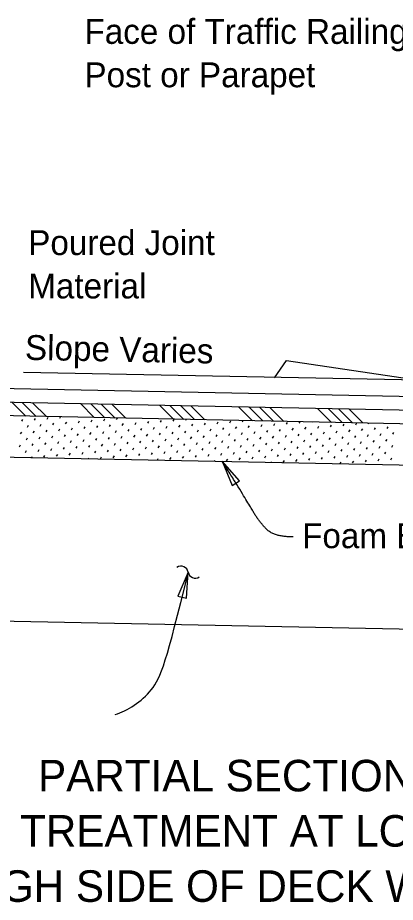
# Model space of a CAD drawing. Extents: x -7.9 to 27, y -3.1 to 14.6.
# Drawn here: x 11.534 to 12.683, y 7.031 to 9.722 of the extents above; entities that cross this region are included whole.
import ezdxf

# ---------------------------------------------------------------- set-up
doc = ezdxf.new("R2010")
doc.units = 0
for name, color, linetype in [('Border', 7, 'Continuous'), ('Patterning', 7, 'Continuous'), ('PlotBorder_dp', 7, 'Continuous'), ('TextMisc', 7, 'Continuous')]:
    doc.layers.add(name, color=color, linetype=linetype)

msp = doc.modelspace()

# ---------------------------------------------------------------- linework, layer by layer
at = {"layer": 'Patterning'}
for p, q in [((11.429, 8.5953), (13.3109, 8.5576)), ((14.5636, 7.8243), (11.2433, 7.8907))]:
    msp.add_line(p, q, dxfattribs=at)
at = {"layer": 'PlotBorder_dp'}
msp.add_lwpolyline([(12.3148, 8.6261), (12.3513, 8.6785), (12.7548, 8.6186), (11.5512, 8.6426)], dxfattribs=at)
for points in [[(12.1563, 8.3723), (12.1863, 8.299), (12.2088, 8.313)], [(12.0528, 8.0347), (12.0215, 7.9619), (12.0472, 7.9557)]]:
    msp.add_lwpolyline(points, close=True, dxfattribs=at)
for centre, start, end in [((12.0306, 8.0307), 10.958, 122.6852), ((12.0744, 8.0392), 190.958, 302.6852)]:
    msp.add_arc(centre, 0.0224, start, end, dxfattribs=at)
for points, degree in [([(12.3717, 8.142), (12.3138, 8.142), (12.2671, 8.1901), (12.2339, 8.2479), (12.1563, 8.3723)], 2), ([(11.8306, 7.6017), (11.8678, 7.6136), (11.9536, 7.6667), (11.9866, 7.7626), (12.0527, 8.0347)], 3)]:
    msp.add_open_spline(points, degree=degree, dxfattribs=at)
at = {"layer": 'TextMisc'}
for p, q in [((11.2433, 8.5573), (13.3732, 8.5146)), ((11.5157, 8.5518), (11.5583, 8.5093)), ((11.5475, 8.5512), (11.5901, 8.5086)), ((11.5794, 8.5505), (11.6219, 8.508)), ((11.7245, 8.5476), (11.767, 8.5051)), ((11.7563, 8.547), (11.7989, 8.5044)), ((11.7881, 8.5464), (11.8307, 8.5038)), ((11.82, 8.5457), (11.8625, 8.5032)), ((11.9651, 8.5428), (12.0076, 8.5003)), ((11.9969, 8.5422), (12.0394, 8.4996)), ((12.0287, 8.5416), (12.0713, 8.499)), ((12.0606, 8.5409), (12.1031, 8.4984)), ((12.2056, 8.538), (12.2482, 8.4954)), ((12.2375, 8.5374), (12.28, 8.4948)), ((12.2693, 8.5367), (12.3119, 8.4942)), ((12.3012, 8.5361), (12.3437, 8.4935)), ((12.4462, 8.5332), (12.4888, 8.4906)), ((12.4781, 8.5326), (12.5206, 8.49)), ((12.5099, 8.5319), (12.5525, 8.4894)), ((12.5417, 8.5313), (12.5843, 8.4887)), ((13.3724, 8.4729), (11.2433, 8.5156)), ((11.6233, 8.5004), (11.6266, 8.506)), ((11.662, 8.5037), (11.664, 8.5071)), ((11.8344, 8.4989), (11.8371, 8.5037)), ((11.546, 8.4939), (11.5492, 8.4995)), ((11.5637, 8.4762), (11.5669, 8.4818)), ((11.5846, 8.4972), (11.5879, 8.5028)), ((11.6024, 8.4795), (11.6056, 8.4851)), ((11.641, 8.4827), (11.6443, 8.4883)), ((11.6797, 8.4859), (11.6829, 8.4915)), ((11.7184, 8.4892), (11.7216, 8.4948)), ((11.7361, 8.4715), (11.7393, 8.4771)), ((11.757, 8.4924), (11.7603, 8.498)), ((11.7747, 8.4747), (11.778, 8.4803)), ((11.7957, 8.4957), (11.7989, 8.5013)), ((11.8134, 8.4779), (11.8167, 8.4835)), ((11.8521, 8.4812), (11.8553, 8.4868)), ((11.873, 8.5021), (11.8735, 8.5029)), ((11.8908, 8.4844), (11.894, 8.49)), ((11.9294, 8.4877), (11.9327, 8.4933)), ((11.9681, 8.4909), (11.9713, 8.4965)), ((11.9858, 8.4732), (11.9891, 8.4788)), ((12.0068, 8.4942), (12.01, 8.4998)), ((12.0245, 8.4764), (12.0277, 8.482)), ((12.0454, 8.4974), (12.0466, 8.4995)), ((12.0632, 8.4797), (12.0664, 8.4853)), ((12.1018, 8.4829), (12.1051, 8.4885)), ((12.1405, 8.4862), (12.1437, 8.4918)), ((12.1792, 8.4894), (12.1824, 8.495)), ((12.1969, 8.4717), (12.2001, 8.4773)), ((12.2178, 8.4926), (12.2198, 8.496)), ((12.2355, 8.4749), (12.2388, 8.4805)), ((12.2742, 8.4782), (12.2775, 8.4838)), ((12.3129, 8.4814), (12.3161, 8.487)), ((12.3516, 8.4847), (12.3548, 8.4902)), ((12.3902, 8.4879), (12.3929, 8.4926)), ((12.4289, 8.4911), (12.4293, 8.4918)), ((12.4466, 8.4734), (12.4499, 8.479)), ((12.4853, 8.4767), (12.4885, 8.4823)), ((12.524, 8.4799), (12.5272, 8.4855)), ((12.5626, 8.4831), (12.5659, 8.4887)), ((12.6013, 8.4864), (12.6024, 8.4884)), ((12.6577, 8.4719), (12.6609, 8.4775)), ((11.5427, 8.4553), (11.546, 8.4609)), ((11.5814, 8.4585), (11.5846, 8.4641)), ((11.6201, 8.4617), (11.6233, 8.4673)), ((11.6587, 8.465), (11.662, 8.4706)), ((11.6765, 8.4473), (11.6797, 8.4529)), ((11.6974, 8.4682), (11.7007, 8.4738)), ((11.7151, 8.4505), (11.7184, 8.4561)), ((11.7538, 8.4538), (11.757, 8.4594)), ((11.7925, 8.457), (11.7957, 8.4626)), ((11.8311, 8.4602), (11.8344, 8.4658)), ((11.8698, 8.4635), (11.873, 8.4691)), ((11.8875, 8.4458), (11.8908, 8.4514)), ((11.9085, 8.4667), (11.9117, 8.4723)), ((11.9262, 8.449), (11.9294, 8.4546)), ((11.9471, 8.47), (11.9504, 8.4756)), ((11.9649, 8.4522), (11.9681, 8.4578)), ((12.0035, 8.4555), (12.0068, 8.4611)), ((12.0422, 8.4587), (12.0454, 8.4643)), ((12.0809, 8.462), (12.0841, 8.4676)), ((12.0986, 8.4443), (12.1018, 8.4498)), ((12.1195, 8.4652), (12.1228, 8.4708)), ((12.1373, 8.4475), (12.1405, 8.4531)), ((12.1582, 8.4684), (12.1614, 8.474)), ((12.1759, 8.4507), (12.1792, 8.4563)), ((12.2146, 8.454), (12.2178, 8.4596)), ((12.2533, 8.4572), (12.2565, 8.4628)), ((12.2919, 8.4605), (12.2952, 8.4661)), ((12.3306, 8.4637), (12.3338, 8.4693)), ((12.3483, 8.446), (12.3516, 8.4516)), ((12.3693, 8.4669), (12.3725, 8.4725)), ((12.387, 8.4492), (12.3902, 8.4548)), ((12.4079, 8.4702), (12.4112, 8.4758)), ((12.4257, 8.4525), (12.4289, 8.4581)), ((12.4643, 8.4557), (12.4676, 8.4613)), ((12.503, 8.4589), (12.5062, 8.4645)), ((12.5417, 8.4622), (12.5449, 8.4678)), ((12.5594, 8.4445), (12.5626, 8.4501)), ((12.5803, 8.4654), (12.5836, 8.471)), ((12.5981, 8.4477), (12.6013, 8.4533)), ((12.619, 8.4687), (12.6222, 8.4743)), ((12.6367, 8.451), (12.64, 8.4566)), ((12.6754, 8.4542), (12.6786, 8.4598)), ((11.5604, 8.4375), (11.5637, 8.4431)), ((11.5782, 8.4198), (11.5814, 8.4254)), ((11.5991, 8.4408), (11.6024, 8.4464)), ((11.6168, 8.4231), (11.6201, 8.4287)), ((11.6378, 8.444), (11.641, 8.4496)), ((11.6555, 8.4263), (11.6587, 8.4319)), ((11.6942, 8.4296), (11.6974, 8.4352)), ((11.7328, 8.4328), (11.7361, 8.4384)), ((11.7715, 8.436), (11.7747, 8.4416)), ((11.7892, 8.4183), (11.7925, 8.4239)), ((11.8102, 8.4393), (11.8134, 8.4449)), ((11.8279, 8.4216), (11.8311, 8.4272)), ((11.8488, 8.4425), (11.8521, 8.4481)), ((11.8666, 8.4248), (11.8698, 8.4304)), ((11.9052, 8.428), (11.9085, 8.4336)), ((11.9439, 8.4313), (11.9471, 8.4369)), ((11.9826, 8.4345), (11.9858, 8.4401)), ((12.0212, 8.4378), (12.0245, 8.4434)), ((12.039, 8.4201), (12.0422, 8.4257)), ((12.0599, 8.441), (12.0632, 8.4466)), ((12.0776, 8.4233), (12.0809, 8.4289)), ((12.1163, 8.4265), (12.1195, 8.4321)), ((12.155, 8.4298), (12.1582, 8.4354)), ((12.1936, 8.433), (12.1969, 8.4386)), ((12.2323, 8.4363), (12.2355, 8.4419)), ((12.25, 8.4185), (12.2533, 8.4241)), ((12.271, 8.4395), (12.2742, 8.4451)), ((12.2887, 8.4218), (12.2919, 8.4274)), ((12.3096, 8.4427), (12.3129, 8.4483)), ((12.3274, 8.425), (12.3306, 8.4306)), ((12.366, 8.4283), (12.3693, 8.4339)), ((12.4047, 8.4315), (12.4079, 8.4371)), ((12.4434, 8.4347), (12.4466, 8.4403)), ((12.482, 8.438), (12.4853, 8.4436)), ((12.4998, 8.4203), (12.503, 8.4259)), ((12.5207, 8.4412), (12.524, 8.4468)), ((12.5384, 8.4235), (12.5417, 8.4291)), ((12.5771, 8.4268), (12.5803, 8.4324)), ((12.6158, 8.43), (12.619, 8.4356)), ((12.6544, 8.4332), (12.6577, 8.4388)), ((11.5395, 8.4166), (11.5427, 8.4222)), ((11.5572, 8.3989), (11.5604, 8.4045)), ((11.5959, 8.4021), (11.5991, 8.4077)), ((11.6345, 8.4054), (11.6378, 8.411)), ((11.6732, 8.4086), (11.6765, 8.4142)), ((11.6909, 8.3909), (11.6942, 8.3965)), ((11.7119, 8.4118), (11.7151, 8.4174)), ((11.7296, 8.3941), (11.7328, 8.3997)), ((11.7506, 8.4151), (11.7538, 8.4207)), ((11.7683, 8.3974), (11.7715, 8.403)), ((11.8069, 8.4006), (11.8102, 8.4062)), ((11.8456, 8.4038), (11.8488, 8.4094)), ((11.8843, 8.4071), (11.8875, 8.4127)), ((11.9229, 8.4103), (11.9262, 8.4159)), ((11.9407, 8.3926), (11.9439, 8.3982)), ((11.9616, 8.4136), (11.9649, 8.4192)), ((11.9793, 8.3959), (11.9826, 8.4015)), ((12.0003, 8.4168), (12.0035, 8.4224)), ((12.018, 8.3991), (12.0212, 8.4047)), ((12.0567, 8.4023), (12.0599, 8.4079)), ((12.0953, 8.4056), (12.0986, 8.4112)), ((12.134, 8.4088), (12.1373, 8.4144)), ((12.1517, 8.3911), (12.155, 8.3967)), ((12.1727, 8.4121), (12.1759, 8.4177)), ((12.1904, 8.3943), (12.1936, 8.3999)), ((12.2114, 8.4153), (12.2146, 8.4209)), ((12.2291, 8.3976), (12.2323, 8.4032)), ((12.2677, 8.4008), (12.271, 8.4064)), ((12.3064, 8.4041), (12.3096, 8.4097)), ((12.3451, 8.4073), (12.3483, 8.4129)), ((12.3837, 8.4106), (12.387, 8.4162)), ((12.4015, 8.3928), (12.4047, 8.3984)), ((12.4224, 8.4138), (12.4257, 8.4194)), ((12.4401, 8.3961), (12.4434, 8.4017)), ((12.4611, 8.417), (12.4643, 8.4226)), ((12.4788, 8.3993), (12.482, 8.4049)), ((12.5175, 8.4026), (12.5207, 8.4082)), ((12.5561, 8.4058), (12.5594, 8.4114)), ((12.5948, 8.409), (12.5981, 8.4146)), ((12.6125, 8.3913), (12.6158, 8.3969)), ((12.6335, 8.4123), (12.6367, 8.4179)), ((12.6512, 8.3946), (12.6544, 8.4002)), ((12.6721, 8.4155), (12.6754, 8.4211)), ((11.2433, 8.3905), (13.3909, 8.3476)), ((11.5765, 8.3839), (11.5782, 8.3868)), ((11.6136, 8.3844), (11.6168, 8.39)), ((11.6523, 8.3876), (11.6555, 8.3932)), ((11.7496, 8.3804), (11.7506, 8.382)), ((11.786, 8.3797), (11.7892, 8.3853)), ((11.8247, 8.3829), (11.8279, 8.3885)), ((11.8633, 8.3861), (11.8666, 8.3917)), ((11.902, 8.3894), (11.9052, 8.395)), ((11.9228, 8.3769), (11.9229, 8.3773)), ((11.9591, 8.3762), (11.9616, 8.3805)), ((11.997, 8.3781), (12.0003, 8.3837)), ((12.0357, 8.3814), (12.039, 8.387)), ((12.0744, 8.3846), (12.0776, 8.3902)), ((12.1131, 8.3879), (12.1163, 8.3935)), ((12.1323, 8.3727), (12.134, 8.3757)), ((12.1694, 8.3734), (12.1727, 8.379)), ((12.2081, 8.3766), (12.2114, 8.3822)), ((12.2468, 8.3799), (12.25, 8.3855)), ((12.2855, 8.3831), (12.2887, 8.3887)), ((12.3054, 8.3693), (12.3064, 8.371)), ((12.3241, 8.3864), (12.3274, 8.392)), ((12.3418, 8.3686), (12.3451, 8.3742)), ((12.3628, 8.3896), (12.366, 8.3952)), ((12.3805, 8.3719), (12.3837, 8.3775)), ((12.4192, 8.3751), (12.4224, 8.3807)), ((12.4578, 8.3784), (12.4611, 8.384)), ((12.4965, 8.3816), (12.4998, 8.3872)), ((12.5149, 8.3651), (12.5175, 8.3695)), ((12.5352, 8.3848), (12.5384, 8.3904)), ((12.5529, 8.3671), (12.5561, 8.3727)), ((12.5739, 8.3881), (12.5771, 8.3937)), ((12.5916, 8.3704), (12.5948, 8.376)), ((12.6302, 8.3736), (12.6335, 8.3792)), ((12.6689, 8.3769), (12.6721, 8.3825)), ((12.4785, 8.3658), (12.4788, 8.3662))]:
    msp.add_line(p, q, dxfattribs=at)

# ---------------------------------------------------------------- texts
at = {"layer": 'Border'}
msp.add_text('Slope Varies', height=0.0756, rotation=358.8543, dxfattribs=at).set_placement((11.5555, 8.681))
msp.add_text('Foam Backer Rod', height=0.0756, dxfattribs=at).set_placement((12.3992, 8.1079))
at = {"layer": 'PlotBorder_dp'}
for s, height, p in [('Face of Traffic Railing, ', 0.0756, (11.737, 9.642)), ('Post or Parapet', 0.0756, (11.737, 9.51)), ('Poured Joint ', 0.0756, (11.5659, 8.9996)), ('Material', 0.0756, (11.5659, 8.8676)), ('PARTIAL SECTION ALONG ℄ JOINT', 0.096, (11.5958, 7.368)), ('JOINT TREATMENT AT LOW SIDE OF DECK OR', 0.096, (11.1347, 7.2)), ('HIGH SIDE OF DECK WITH SLOPES < 1%', 0.096, (11.3543, 7.032))]:
    msp.add_text(s, height=height, dxfattribs=at).set_placement(p)

doc.saveas('drawing.dxf')
